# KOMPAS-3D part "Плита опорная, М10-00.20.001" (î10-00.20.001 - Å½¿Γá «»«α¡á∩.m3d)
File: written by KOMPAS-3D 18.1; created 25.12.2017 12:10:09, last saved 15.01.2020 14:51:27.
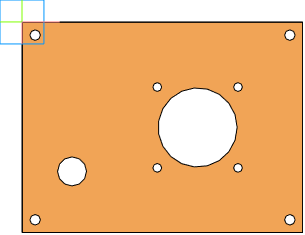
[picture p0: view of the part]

Document properties: Автор: Мирончук; Организация: Мирончук; Полное имя файла: D:\Magna\Магна Ins\Магна ins 10\М10-00.00.000\3Д\М10-00.20.001 - Плита опорная.m3d

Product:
- Part/product: Плита опорная  | designation М10-00.20.001
    Масса: 2.06392
    Раздел спецификации: Детали
    Форматы листов документа: A3
- Part/product: Плита опорная  | designation М10-00.20.001-01
    Масса: 1.84628
    Раздел спецификации: Детали
    Форматы листов документа: A3

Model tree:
1. Эскиз:1
2. Операция выдавливания:1
     Расстояние 1 = 15
3. Фаска:1  (with: Операция выдавливания:1)  (labels: М10-00.20.000 - Корпус.a3d)
     Угол = 45; Длина 1 = 0.5; Длина 2 = 0.5

Expressions: (v10-v21)/2; (v9-v20)/2
Referenced files in D:\Magna\Магна Ins\Магна ins 10\М10-00.00.000\3Д\: М10-00.20.000 - Корпус.a3d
